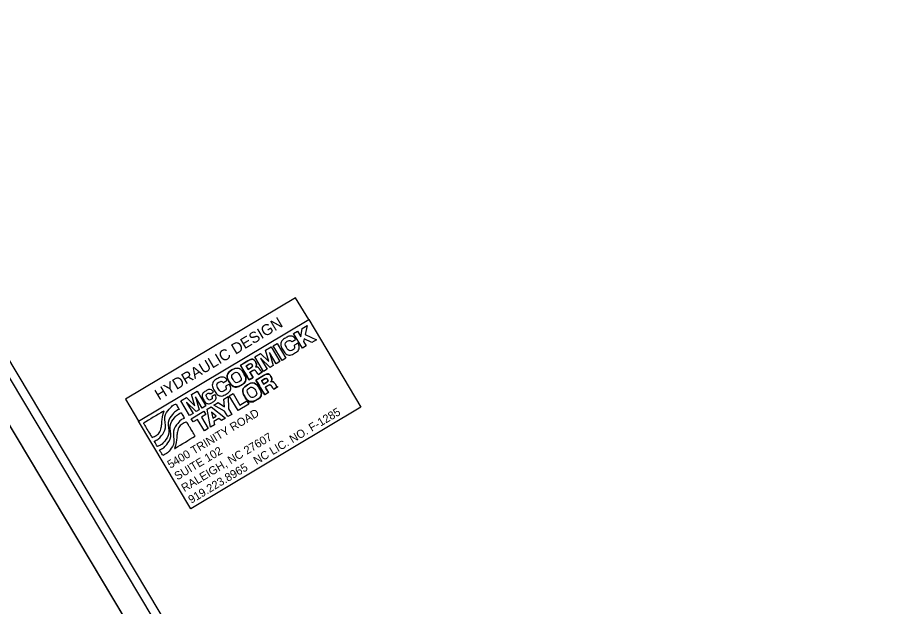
# Model space of a CAD drawing. Extents: x 1487794 to 1489801, y 498102 to 499906.
# Drawn here: x 1489348.7 to 1489801.1, y 499604.6 to 499905.6 of the extents above; entities that cross this region are included whole.
import ezdxf

# ---------------------------------------------------------------- set-up
doc = ezdxf.new("R2010")
doc.units = 0
for name, color, linetype in [('Exist Vertical Profile Ground Line', 7, 'Continuous'), ('Exist Vertical Profile Horizontal Axis Label Major', 7, 'Continuous'), ('Prop Terminator CELL', 7, 'Continuous'), ('Prop Vertical Profile Curve Label', 7, 'Continuous'), ('Sheet Layout Profile Border Port 2', 7, 'Continuous'), ('Sheet Profile Grid Middle CELL', 7, 'Continuous')]:
    doc.layers.add(name, color=color, linetype=linetype)

msp = doc.modelspace()

# ---------------------------------------------------------------- linework, layer by layer
at = {"layer": 'Exist Vertical Profile Ground Line'}
msp.add_lwpolyline([(1488356.6, 498126.17), (1489787.01, 498980.28), (1489246.14, 499886.09), (1487815.74, 499031.98)], close=True, dxfattribs=at)
at = {"layer": 'Exist Vertical Profile Horizontal Axis Label Major'}
msp.add_lwpolyline([(1488355.69, 498102.34), (1489801.12, 498965.41), (1489239.75, 499905.57), (1487794.32, 499042.49)], close=True, dxfattribs=at)
at = {"layer": 'Prop Terminator CELL'}
msp.add_lwpolyline([(1488230.78, 498636.31), (1487948.81, 499108.53), (1489064.93, 499774.97), (1489153.91, 499625.97), (1489135.02, 499614.69), (1489151.4, 499587.25), (1489342.04, 499701.08), (1489518.66, 499405.31)], close=True, dxfattribs=at)
at = {"layer": 'Prop Vertical Profile Curve Label'}
for p, q in [((1489489.8, 499744.09), (1489491.76, 499745.26)), ((1489494.28, 499736.6), (1489489.8, 499744.09)), ((1489491.76, 499745.26), (1489493.48, 499742.38)), ((1489493.48, 499742.38), (1489494.22, 499746.73)), ((1489494.22, 499746.73), (1489496.65, 499748.18)), ((1489496.65, 499748.18), (1489495.64, 499743.57)), ((1489495.15, 499741.39), (1489494.85, 499740.07)), ((1489494.85, 499740.07), (1489496.23, 499737.76)), ((1489499.05, 499739.44), (1489495.15, 499741.39)), ((1489495.64, 499743.57), (1489501.47, 499740.89)), ((1489501.47, 499740.89), (1489499.05, 499739.44)), ((1489475.4, 499735.49), (1489478.28, 499737.21)), ((1489477.09, 499729.72), (1489475.4, 499735.49)), ((1489478.28, 499737.21), (1489482.75, 499729.71)), ((1489479.37, 499737.86), (1489481.32, 499739.03)), ((1489483.85, 499730.36), (1489479.37, 499737.86)), ((1489481.32, 499739.03), (1489485.8, 499731.53)), ((1489496.23, 499737.76), (1489494.28, 499736.6)), ((1489469.92, 499732.22), (1489472.8, 499733.94)), ((1489474.4, 499724.72), (1489469.92, 499732.22)), ((1489472.8, 499733.94), (1489477.07, 499729.71)), ((1489472.86, 499731.52), (1489472.84, 499731.51)), ((1489472.84, 499731.51), (1489476.23, 499725.82)), ((1489477.83, 499726.77), (1489472.86, 499731.52)), ((1489477.52, 499734.31), (1489477.5, 499734.29)), ((1489477.5, 499734.29), (1489479.32, 499727.66)), ((1489480.92, 499728.62), (1489477.52, 499734.31)), ((1489485.8, 499731.53), (1489483.85, 499730.36)), ((1489470.24, 499727), (1489470.26, 499726.98)), ((1489476.23, 499725.82), (1489474.4, 499724.72)), ((1489477.07, 499729.71), (1489477.09, 499729.72)), ((1489479.32, 499727.66), (1489477.83, 499726.77)), ((1489482.75, 499729.71), (1489480.92, 499728.62)), ((1489473.74, 499724.33), (1489471.81, 499723.18)), ((1489478.17, 499719.46), (1489478.18, 499719.44)), ((1489481.67, 499716.79), (1489479.73, 499715.64)), ((1489437.51, 499712.86), (1489440.39, 499714.58)), ((1489439.2, 499707.1), (1489437.51, 499712.86)), ((1489440.39, 499714.58), (1489444.86, 499707.09)), ((1489456.9, 499712.17), (1489458.85, 499713.34)), ((1489461.38, 499704.68), (1489456.9, 499712.17)), ((1489458.85, 499713.34), (1489462.33, 499707.52)), ((1489432.03, 499709.59), (1489434.91, 499711.31)), ((1489436.5, 499702.1), (1489432.03, 499709.59)), ((1489434.91, 499711.31), (1489439.18, 499707.08)), ((1489434.97, 499708.9), (1489434.94, 499708.88)), ((1489434.94, 499708.88), (1489438.34, 499703.19)), ((1489439.94, 499704.15), (1489434.97, 499708.9)), ((1489439.63, 499711.68), (1489439.61, 499711.67)), ((1489439.61, 499711.67), (1489441.43, 499705.04)), ((1489443.02, 499705.99), (1489439.63, 499711.68)), ((1489448.97, 499707.44), (1489451.19, 499708.76)), ((1489451.19, 499708.76), (1489454.5, 499706.61)), ((1489454.17, 499710.54), (1489456.39, 499711.86)), ((1489454.5, 499706.61), (1489454.17, 499710.54)), ((1489456.39, 499711.86), (1489456.46, 499705.53)), ((1489466.83, 499707.93), (1489461.38, 499704.68)), ((1489462.33, 499707.52), (1489465.82, 499709.61)), ((1489465.82, 499709.61), (1489466.83, 499707.93)), ((1489438.34, 499703.19), (1489436.5, 499702.1)), ((1489437.43, 499700.54), (1489443.86, 499704.38)), ((1489439.18, 499707.08), (1489439.2, 499707.1)), ((1489441.43, 499705.04), (1489439.94, 499704.15)), ((1489444.86, 499707.09), (1489443.02, 499705.99)), ((1489443.86, 499704.38), (1489444.86, 499702.7)), ((1489445.61, 499705.43), (1489447.59, 499706.61)), ((1489447.28, 499696.26), (1489445.61, 499705.43)), ((1489447.59, 499706.61), (1489454.87, 499700.79)), ((1489447.85, 499703.95), (1489447.83, 499703.93)), ((1489447.83, 499703.93), (1489448.54, 499700.8)), ((1489450.25, 499701.82), (1489447.85, 499703.95)), ((1489454.51, 499704.36), (1489448.97, 499707.44)), ((1489456.18, 499701.57), (1489454.51, 499704.36)), ((1489456.46, 499705.53), (1489458.13, 499702.74)), ((1489438.43, 499698.87), (1489437.43, 499700.54)), ((1489440.67, 499700.2), (1489438.43, 499698.87)), ((1489444.14, 499694.38), (1489440.67, 499700.2)), ((1489444.86, 499702.7), (1489442.62, 499701.37)), ((1489442.62, 499701.37), (1489446.1, 499695.55)), ((1489448.54, 499700.8), (1489450.25, 499701.82)), ((1489451.57, 499700.64), (1489448.96, 499699.08)), ((1489448.96, 499699.08), (1489449.29, 499697.46)), ((1489452.84, 499699.58), (1489451.57, 499700.64)), ((1489454.87, 499700.79), (1489452.84, 499699.58)), ((1489458.13, 499702.74), (1489456.18, 499701.57)), ((1489446.1, 499695.55), (1489444.14, 499694.38)), ((1489449.29, 499697.46), (1489447.28, 499696.26))]:
    msp.add_line(p, q, dxfattribs=at)
for points in [[(1489410.49, 499699.26), (1489497.49, 499751.21), (1489490.81, 499762.41), (1489403.81, 499710.46)], [(1489410.49, 499699.26), (1489497.49, 499751.21), (1489524.22, 499706.46), (1489437.21, 499654.51)]]:
    msp.add_lwpolyline(points, close=True, dxfattribs=at)
for points in [[(1489489.8, 499744.09), (1489491.76, 499745.26), (1489493.48, 499742.38), (1489494.22, 499746.73), (1489496.65, 499748.18), (1489495.64, 499743.57), (1489501.47, 499740.89), (1489499.05, 499739.44), (1489495.15, 499741.39), (1489494.85, 499740.07), (1489496.23, 499737.76), (1489494.28, 499736.6), (1489489.8, 499744.09)], [(1489469.92, 499732.22), (1489472.8, 499733.94), (1489477.07, 499729.71), (1489477.09, 499729.72), (1489475.4, 499735.49), (1489478.28, 499737.21), (1489482.75, 499729.71), (1489480.92, 499728.62), (1489477.52, 499734.31), (1489477.5, 499734.29), (1489479.32, 499727.66), (1489477.83, 499726.77), (1489472.86, 499731.52), (1489472.84, 499731.51), (1489476.23, 499725.82), (1489474.4, 499724.72), (1489469.92, 499732.22)], [(1489479.37, 499737.86), (1489481.32, 499739.03), (1489485.8, 499731.53), (1489483.85, 499730.36), (1489479.37, 499737.86)], [(1489468.87, 499725.13), (1489467.39, 499724.24), (1489469.02, 499721.51), (1489467.07, 499720.35), (1489462.59, 499727.84), (1489466.41, 499730.12)], [(1489467.03, 499728.37), (1489465.48, 499727.44), (1489466.49, 499725.75), (1489468.13, 499726.73)], [(1489476.79, 499717.58), (1489475.31, 499716.7), (1489476.94, 499713.97), (1489474.99, 499712.8), (1489470.51, 499720.3), (1489474.34, 499722.58)], [(1489474.95, 499720.83), (1489473.4, 499719.9), (1489474.41, 499718.21), (1489476.05, 499719.19)], [(1489432.03, 499709.59), (1489434.91, 499711.31), (1489439.18, 499707.08), (1489439.2, 499707.1), (1489437.51, 499712.86), (1489440.39, 499714.58), (1489444.86, 499707.09), (1489443.02, 499705.99), (1489439.63, 499711.68), (1489439.61, 499711.67), (1489441.43, 499705.04), (1489439.94, 499704.15), (1489434.97, 499708.9), (1489434.94, 499708.88), (1489438.34, 499703.19), (1489436.5, 499702.1), (1489432.03, 499709.59)], [(1489456.9, 499712.17), (1489458.85, 499713.34), (1489462.33, 499707.52), (1489465.82, 499709.61), (1489466.83, 499707.93), (1489461.38, 499704.68), (1489456.9, 499712.17)], [(1489456.46, 499705.53), (1489458.13, 499702.74), (1489456.18, 499701.57), (1489454.51, 499704.36), (1489448.97, 499707.44), (1489451.19, 499708.76), (1489454.5, 499706.61), (1489454.17, 499710.54), (1489456.39, 499711.86), (1489456.46, 499705.53)], [(1489444.86, 499702.7), (1489442.62, 499701.37), (1489446.1, 499695.55), (1489444.14, 499694.38), (1489440.67, 499700.2), (1489438.43, 499698.87), (1489437.43, 499700.54), (1489443.86, 499704.38), (1489444.86, 499702.7)], [(1489445.61, 499705.43), (1489447.59, 499706.61), (1489454.87, 499700.79), (1489452.84, 499699.58), (1489451.57, 499700.64), (1489448.96, 499699.08), (1489449.29, 499697.46), (1489447.28, 499696.26), (1489445.61, 499705.43)], [(1489448.54, 499700.8), (1489450.25, 499701.82), (1489447.85, 499703.95), (1489447.83, 499703.93), (1489448.54, 499700.8)]]:
    msp.add_lwpolyline(points, dxfattribs=at)
for points in [[(1489488.83, 499739.88), (1489488.27, 499740.57), (1489487.45, 499740.62), (1489486.63, 499740.13), (1489485.37, 499739.38), (1489485.55, 499737.98), (1489486.22, 499736.86), (1489486.88, 499735.75), (1489488.03, 499734.93), (1489489.29, 499735.68), (1489490.2, 499736.22), (1489490.41, 499737.06), (1489489.97, 499737.97), (1489489.97, 499737.97), (1489491.92, 499739.13), (1489491.92, 499739.13), (1489492.97, 499737.14), (1489492.23, 499735.16), (1489490.33, 499734.02), (1489488.06, 499732.67), (1489485.56, 499733.53), (1489484.26, 499735.7), (1489482.97, 499737.87), (1489483.4, 499740.48), (1489485.67, 499741.84), (1489487.29, 499742.8), (1489489.65, 499742.82), (1489490.78, 499741.04), (1489490.78, 499741.04), (1489488.83, 499739.88), (1489488.83, 499739.88)], [(1489488.83, 499739.88), (1489488.27, 499740.57), (1489487.45, 499740.62), (1489486.63, 499740.13), (1489485.37, 499739.38), (1489485.55, 499737.98), (1489486.22, 499736.86), (1489486.88, 499735.75), (1489488.03, 499734.93), (1489489.29, 499735.68), (1489490.2, 499736.22), (1489490.41, 499737.06), (1489489.97, 499737.97), (1489489.97, 499737.97), (1489491.92, 499739.13), (1489491.92, 499739.13), (1489492.97, 499737.14), (1489492.23, 499735.16), (1489490.33, 499734.02), (1489488.06, 499732.67), (1489485.56, 499733.53), (1489484.26, 499735.7), (1489482.97, 499737.87), (1489483.4, 499740.48), (1489485.67, 499741.84), (1489487.29, 499742.8), (1489489.65, 499742.82), (1489490.78, 499741.04), (1489490.78, 499741.04), (1489488.83, 499739.88), (1489488.83, 499739.88)], [(1489462.59, 499727.84), (1489462.59, 499727.84), (1489466.41, 499730.12), (1489466.41, 499730.12), (1489467.74, 499730.91), (1489469.4, 499731.09), (1489470.3, 499729.58), (1489470.78, 499728.77), (1489470.85, 499727.78), (1489470.24, 499727), (1489470.24, 499727), (1489470.26, 499726.98), (1489470.26, 499726.98), (1489471.17, 499727.27), (1489471.93, 499726.51), (1489472.42, 499725.84), (1489472.63, 499725.53), (1489473.32, 499724.45), (1489473.74, 499724.33), (1489473.74, 499724.33), (1489471.81, 499723.18), (1489471.81, 499723.18), (1489471.49, 499723.33), (1489471.02, 499724.05), (1489470.88, 499724.25), (1489470.37, 499724.97), (1489469.78, 499725.67), (1489468.87, 499725.13), (1489468.87, 499725.13), (1489467.39, 499724.24), (1489467.39, 499724.24), (1489467.39, 499724.24), (1489469.02, 499721.51), (1489469.02, 499721.51), (1489469.02, 499721.51), (1489467.07, 499720.35), (1489467.07, 499720.35), (1489467.07, 499720.35), (1489462.59, 499727.84), (1489462.59, 499727.84)], [(1489466.41, 499730.12), (1489467.74, 499730.91), (1489469.4, 499731.09), (1489470.3, 499729.58), (1489470.78, 499728.77), (1489470.85, 499727.78), (1489470.24, 499727)], [(1489458.22, 499725.45), (1489460.59, 499726.86), (1489462.95, 499725.92), (1489464.25, 499723.75), (1489465.55, 499721.58), (1489465.25, 499719.05), (1489462.89, 499717.64), (1489460.52, 499716.23), (1489458.16, 499717.16), (1489456.86, 499719.34), (1489455.56, 499721.51), (1489455.86, 499724.04), (1489458.22, 499725.45)], [(1489458.22, 499725.45), (1489460.59, 499726.86), (1489462.95, 499725.92), (1489464.25, 499723.75), (1489465.55, 499721.58), (1489465.25, 499719.05), (1489462.89, 499717.64), (1489462.56, 499717.44), (1489462.24, 499717.29), (1489461.92, 499717.19)], [(1489466.49, 499725.75), (1489466.49, 499725.75), (1489468.13, 499726.73), (1489468.13, 499726.73), (1489468.71, 499727.08), (1489468.84, 499727.59), (1489468.5, 499728.15), (1489468.17, 499728.71), (1489467.58, 499728.7), (1489467.03, 499728.37), (1489467.03, 499728.37), (1489465.48, 499727.44), (1489465.48, 499727.44), (1489465.48, 499727.44), (1489466.49, 499725.75), (1489466.49, 499725.75)], [(1489468.13, 499726.73), (1489468.71, 499727.08), (1489468.84, 499727.59), (1489468.5, 499728.15), (1489468.17, 499728.71), (1489467.58, 499728.7), (1489467.03, 499728.37)], [(1489470.26, 499726.98), (1489471.17, 499727.27), (1489471.93, 499726.51), (1489472.42, 499725.84), (1489472.63, 499725.53), (1489473.32, 499724.45), (1489473.74, 499724.33)], [(1489453.82, 499718.97), (1489453.26, 499719.66), (1489452.43, 499719.71), (1489451.61, 499719.22), (1489450.36, 499718.47), (1489450.54, 499717.07), (1489451.2, 499715.96), (1489451.87, 499714.84), (1489453.01, 499714.02), (1489454.27, 499714.77), (1489455.19, 499715.32), (1489455.4, 499716.16), (1489454.96, 499717.06), (1489454.96, 499717.06), (1489456.91, 499718.23), (1489456.91, 499718.23), (1489457.96, 499716.23), (1489457.22, 499714.25), (1489455.32, 499713.12), (1489453.05, 499711.76), (1489450.55, 499712.62), (1489449.25, 499714.79), (1489447.95, 499716.96), (1489448.39, 499719.57), (1489450.65, 499720.93), (1489452.27, 499721.89), (1489454.64, 499721.91), (1489455.77, 499720.14), (1489455.77, 499720.14), (1489453.82, 499718.97), (1489453.82, 499718.97)], [(1489453.82, 499718.97), (1489453.26, 499719.66), (1489452.43, 499719.71), (1489451.61, 499719.22), (1489450.36, 499718.47), (1489450.54, 499717.07), (1489451.2, 499715.96), (1489451.87, 499714.84), (1489453.01, 499714.02), (1489454.27, 499714.77), (1489455.19, 499715.32), (1489455.4, 499716.16), (1489454.96, 499717.06), (1489454.96, 499717.06), (1489456.91, 499718.23), (1489456.91, 499718.23), (1489457.96, 499716.23), (1489457.22, 499714.25), (1489455.32, 499713.12), (1489453.05, 499711.76), (1489450.55, 499712.62), (1489449.25, 499714.79), (1489447.95, 499716.96), (1489448.39, 499719.57), (1489450.65, 499720.93), (1489452.27, 499721.89), (1489454.64, 499721.91), (1489455.77, 499720.14), (1489455.77, 499720.14), (1489453.82, 499718.97), (1489453.82, 499718.97)], [(1489461.92, 499717.19), (1489459.9, 499716.51), (1489457.98, 499717.46), (1489456.86, 499719.34), (1489455.56, 499721.51), (1489455.86, 499724.04), (1489458.22, 499725.45)], [(1489461.88, 499719.32), (1489463.14, 499720.07), (1489462.96, 499721.47), (1489462.3, 499722.58), (1489461.63, 499723.7), (1489460.49, 499724.52), (1489459.23, 499723.77), (1489457.97, 499723.02), (1489458.15, 499721.61), (1489458.81, 499720.5), (1489459.48, 499719.39), (1489460.62, 499718.56), (1489461.88, 499719.32)], [(1489461.88, 499719.32), (1489463.14, 499720.07), (1489462.96, 499721.47), (1489462.3, 499722.58), (1489461.63, 499723.7), (1489460.49, 499724.52), (1489459.23, 499723.77), (1489457.97, 499723.02), (1489458.15, 499721.61), (1489458.81, 499720.5), (1489459.48, 499719.39), (1489460.62, 499718.56), (1489461.88, 499719.32)], [(1489471.81, 499723.18), (1489471.49, 499723.33), (1489471.02, 499724.05), (1489470.88, 499724.25), (1489470.37, 499724.97), (1489469.78, 499725.67), (1489468.87, 499725.13)], [(1489470.51, 499720.3), (1489470.51, 499720.3), (1489474.34, 499722.58), (1489474.34, 499722.58), (1489475.66, 499723.37), (1489477.32, 499723.55), (1489478.22, 499722.04), (1489478.7, 499721.23), (1489478.77, 499720.23), (1489478.17, 499719.46), (1489478.17, 499719.46), (1489478.18, 499719.44), (1489478.18, 499719.44), (1489479.09, 499719.72), (1489479.85, 499718.97), (1489480.34, 499718.29), (1489480.55, 499717.99), (1489481.24, 499716.91), (1489481.67, 499716.79), (1489481.67, 499716.79), (1489479.73, 499715.64), (1489479.73, 499715.64), (1489479.42, 499715.79), (1489478.95, 499716.5), (1489478.8, 499716.7), (1489478.3, 499717.43), (1489477.71, 499718.13), (1489476.79, 499717.58), (1489476.79, 499717.58), (1489475.31, 499716.7), (1489475.31, 499716.7), (1489475.31, 499716.7), (1489476.94, 499713.97), (1489476.94, 499713.97), (1489476.94, 499713.97), (1489474.99, 499712.8), (1489474.99, 499712.8), (1489474.99, 499712.8), (1489470.51, 499720.3), (1489470.51, 499720.3)], [(1489474.34, 499722.58), (1489475.66, 499723.37), (1489477.32, 499723.55), (1489478.22, 499722.04), (1489478.7, 499721.23), (1489478.77, 499720.23), (1489478.17, 499719.46)], [(1489466.15, 499717.91), (1489468.52, 499719.32), (1489470.88, 499718.38), (1489472.18, 499716.21), (1489473.48, 499714.04), (1489473.18, 499711.51), (1489470.82, 499710.1), (1489468.46, 499708.69), (1489466.09, 499709.62), (1489464.79, 499711.8), (1489463.49, 499713.97), (1489463.79, 499716.5), (1489466.15, 499717.91)], [(1489469.85, 499709.65), (1489467.83, 499708.97), (1489465.91, 499709.92), (1489464.79, 499711.8), (1489463.49, 499713.97), (1489463.79, 499716.5), (1489466.15, 499717.91)], [(1489469.82, 499711.78), (1489471.08, 499712.53), (1489470.89, 499713.93), (1489470.23, 499715.05), (1489469.56, 499716.16), (1489468.42, 499716.98), (1489467.16, 499716.23), (1489465.9, 499715.48), (1489466.08, 499714.08), (1489466.74, 499712.96), (1489467.41, 499711.85), (1489468.56, 499711.03), (1489469.82, 499711.78)], [(1489469.82, 499711.78), (1489471.08, 499712.53), (1489470.89, 499713.93), (1489470.23, 499715.05), (1489469.56, 499716.16), (1489468.42, 499716.98), (1489467.16, 499716.23), (1489465.9, 499715.48), (1489466.08, 499714.08), (1489466.74, 499712.96), (1489467.41, 499711.85), (1489468.56, 499711.03), (1489469.82, 499711.78)], [(1489466.15, 499717.91), (1489468.52, 499719.32), (1489470.88, 499718.38), (1489472.18, 499716.21), (1489473.48, 499714.04), (1489473.18, 499711.51), (1489470.82, 499710.1), (1489470.5, 499709.91), (1489470.17, 499709.76), (1489469.85, 499709.65)], [(1489474.41, 499718.21), (1489474.41, 499718.21), (1489476.05, 499719.19), (1489476.05, 499719.19), (1489476.64, 499719.54), (1489476.76, 499720.04), (1489476.42, 499720.61), (1489476.09, 499721.17), (1489475.5, 499721.15), (1489474.95, 499720.83), (1489474.95, 499720.83), (1489473.4, 499719.9), (1489473.4, 499719.9), (1489473.4, 499719.9), (1489474.41, 499718.21), (1489474.41, 499718.21)], [(1489476.05, 499719.19), (1489476.64, 499719.54), (1489476.76, 499720.04), (1489476.42, 499720.61), (1489476.09, 499721.17), (1489475.5, 499721.15), (1489474.95, 499720.83)], [(1489479.73, 499715.64), (1489479.42, 499715.79), (1489478.95, 499716.5), (1489478.8, 499716.7), (1489478.3, 499717.43), (1489477.71, 499718.13), (1489476.79, 499717.58)], [(1489478.18, 499719.44), (1489479.09, 499719.72), (1489479.85, 499718.97), (1489480.34, 499718.29), (1489480.55, 499717.99), (1489481.24, 499716.91), (1489481.67, 499716.79)], [(1489447.14, 499713.13), (1489446.86, 499713.59), (1489446.25, 499713.67), (1489445.8, 499713.4), (1489444.8, 499712.81), (1489445.15, 499711.86), (1489445.61, 499711.11), (1489446.03, 499710.4), (1489446.76, 499709.86), (1489447.52, 499710.31), (1489448.14, 499710.68), (1489448.24, 499711.23), (1489447.98, 499711.85), (1489447.98, 499711.85), (1489449.71, 499712.89), (1489449.71, 499712.89), (1489450.42, 499711.33), (1489449.79, 499709.82), (1489448.34, 499708.95), (1489446.71, 499707.98), (1489444.82, 499708.37), (1489443.82, 499710.04), (1489442.79, 499711.77), (1489443.15, 499713.67), (1489444.9, 499714.72), (1489446.26, 499715.52), (1489447.89, 499715.53), (1489448.87, 499714.17), (1489448.87, 499714.17), (1489447.14, 499713.13), (1489447.14, 499713.13)], [(1489447.14, 499713.13), (1489446.86, 499713.59), (1489446.25, 499713.67), (1489445.8, 499713.4), (1489444.8, 499712.81), (1489445.15, 499711.86), (1489445.61, 499711.11), (1489446.03, 499710.4), (1489446.76, 499709.86), (1489447.52, 499710.31), (1489448.14, 499710.68), (1489448.24, 499711.23), (1489447.98, 499711.85), (1489447.98, 499711.85), (1489449.71, 499712.89), (1489449.71, 499712.89), (1489450.42, 499711.33), (1489449.79, 499709.82), (1489448.34, 499708.95), (1489446.71, 499707.98), (1489444.82, 499708.37), (1489443.82, 499710.04), (1489442.79, 499711.77), (1489443.15, 499713.67), (1489444.9, 499714.72), (1489446.26, 499715.52), (1489447.89, 499715.53), (1489448.87, 499714.17), (1489448.87, 499714.17), (1489447.14, 499713.13), (1489447.14, 499713.13)], [(1489420.16, 499686.23), (1489421.13, 499686.8), (1489422.15, 499687.06), (1489423.63, 499688.72), (1489426.74, 499692.69), (1489424.72, 499699.04), (1489428.05, 499702.95), (1489429.88, 499704.89), (1489431.27, 499705.24), (1489431.27, 499705.24), (1489431.27, 499705.24), (1489429.61, 499708.01), (1489429.61, 499708.01), (1489429.61, 499708.01), (1489428.22, 499707.66), (1489426.39, 499705.72), (1489423.06, 499701.82), (1489425.08, 499695.46), (1489421.98, 499691.5), (1489420.49, 499689.83), (1489419.47, 499689.57), (1489418.51, 499689), (1489418.51, 499689), (1489420.16, 499686.23), (1489420.16, 499686.23)], [(1489420.16, 499686.23), (1489421.13, 499686.8), (1489422.15, 499687.06), (1489423.63, 499688.72), (1489426.74, 499692.69), (1489424.72, 499699.04), (1489428.05, 499702.95), (1489429.88, 499704.89), (1489431.27, 499705.24), (1489431.27, 499705.24), (1489431.27, 499705.24), (1489429.61, 499708.01), (1489429.61, 499708.01), (1489429.61, 499708.01), (1489428.22, 499707.66), (1489426.39, 499705.72), (1489423.06, 499701.82), (1489425.08, 499695.46), (1489421.98, 499691.5), (1489420.49, 499689.83), (1489419.47, 499689.57), (1489418.51, 499689), (1489418.51, 499689), (1489420.16, 499686.23), (1489420.16, 499686.23)], [(1489423.6, 499704.58), (1489422.68, 499702.39), (1489422.41, 499698.29), (1489422.2, 499696.92), (1489421.66, 499693.56), (1489419.73, 499691.92), (1489417.39, 499690.87), (1489417.39, 499690.87), (1489412.99, 499698.24), (1489412.99, 499698.24), (1489412.99, 499698.24), (1489423.6, 499704.58), (1489423.6, 499704.58)], [(1489423.6, 499704.58), (1489422.68, 499702.39), (1489422.41, 499698.29), (1489422.2, 499696.92), (1489421.66, 499693.56), (1489419.73, 499691.92), (1489417.39, 499690.87), (1489417.39, 499690.87), (1489412.99, 499698.24), (1489412.99, 499698.24), (1489412.99, 499698.24), (1489423.6, 499704.58), (1489423.6, 499704.58)], [(1489422.84, 499681.74), (1489423.81, 499682.32), (1489424.82, 499682.58), (1489426.31, 499684.24), (1489429.42, 499688.2), (1489427.4, 499694.56), (1489430.73, 499698.47), (1489432.55, 499700.4), (1489433.95, 499700.76), (1489433.95, 499700.76), (1489433.95, 499700.76), (1489432.29, 499703.53), (1489432.29, 499703.53), (1489432.29, 499703.53), (1489430.9, 499703.18), (1489429.07, 499701.24), (1489425.74, 499697.34), (1489427.76, 499690.98), (1489424.65, 499687.01), (1489423.17, 499685.35), (1489422.15, 499685.09), (1489421.19, 499684.52), (1489421.19, 499684.52), (1489422.84, 499681.74), (1489422.84, 499681.74)], [(1489422.84, 499681.74), (1489423.81, 499682.32), (1489424.82, 499682.58), (1489426.31, 499684.24), (1489429.42, 499688.2), (1489427.4, 499694.56), (1489430.73, 499698.47), (1489432.55, 499700.4), (1489433.95, 499700.76), (1489433.95, 499700.76), (1489433.95, 499700.76), (1489432.29, 499703.53), (1489432.29, 499703.53), (1489432.29, 499703.53), (1489430.9, 499703.18), (1489429.07, 499701.24), (1489425.74, 499697.34), (1489427.76, 499690.98), (1489424.65, 499687.01), (1489423.17, 499685.35), (1489422.15, 499685.09), (1489421.19, 499684.52), (1489421.19, 499684.52), (1489422.84, 499681.74), (1489422.84, 499681.74)], [(1489428.82, 499685.23), (1489429.74, 499687.42), (1489430.01, 499691.52), (1489430.23, 499692.89), (1489430.76, 499696.25), (1489432.69, 499697.9), (1489435.03, 499698.94), (1489435.03, 499698.94), (1489439.43, 499691.57), (1489439.43, 499691.57), (1489439.43, 499691.57), (1489428.82, 499685.23), (1489428.82, 499685.23)], [(1489428.82, 499685.23), (1489429.74, 499687.42), (1489430.01, 499691.52), (1489430.23, 499692.89), (1489430.76, 499696.25), (1489432.69, 499697.9), (1489435.03, 499698.94), (1489435.03, 499698.94), (1489439.43, 499691.57), (1489439.43, 499691.57), (1489439.43, 499691.57), (1489428.82, 499685.23), (1489428.82, 499685.23)]]:
    msp.add_open_spline(points, degree=3, dxfattribs=at)
at = {"layer": 'Sheet Profile Grid Middle CELL'}
msp.add_lwpolyline([(1489236.69, 499877.53), (1487948.81, 499108.53), (1488487.11, 498207.01), (1489774.99, 498976.02)], close=True, dxfattribs=at)

# ---------------------------------------------------------------- texts
at = {"layer": 'Prop Vertical Profile Curve Label'}
for s, height, p in [('5400 TRINITY ROAD', 4.1773, (1489426.75, 499674.91)), ('919.223.8965   NC LIC. NO. F-1285', 4.1773, (1489437.46, 499656.98)), ('RALEIGH, NC 27607', 4.1773, (1489433.89, 499662.95)), ('SUITE 102', 4.177, (1489430.32, 499668.93))]:
    msp.add_text(s, height=height, rotation=30.8418, dxfattribs=at).set_placement(p)
at = {"layer": 'Sheet Layout Profile Border Port 2'}
msp.add_text('HYDRAULIC DESIGN', height=5.625, rotation=30.8418, dxfattribs=at).set_placement((1489420.91, 499709.8))

doc.saveas('drawing.dxf')
